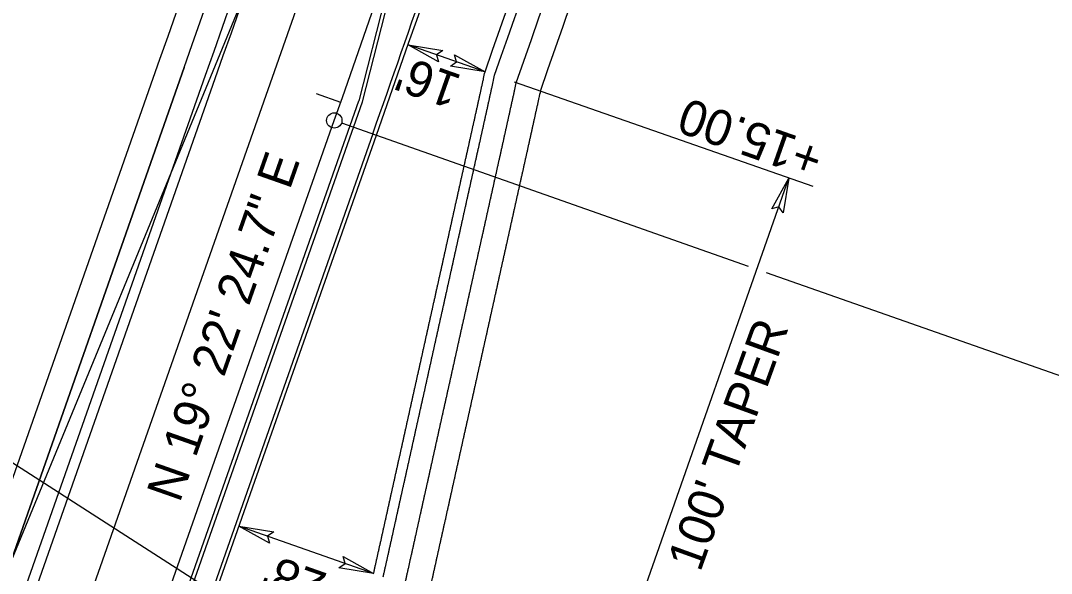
# Model space of a CAD drawing. Extents: x 1974386 to 1979988, y 776712 to 784860.
# Drawn here: x 1977395.6 to 1977597.8, y 780987 to 781095.4 of the extents above; entities that cross this region are included whole.
import ezdxf

# ---------------------------------------------------------------- set-up
doc = ezdxf.new("R2010")
doc.units = 0
for name, color, linetype in [('Prop Conc 2ft 6in Curb and Gutter', 7, 'Continuous'), ('Prop Conc 4in Sidewalk', 7, 'Continuous'), ('Prop Conc 5in Monolithic Keyed In Island', 7, 'Continuous'), ('Prop Dimension', 7, 'Continuous'), ('Prop Dimension Text', 7, 'Continuous'), ('Prop EOT', 7, 'Continuous'), ('Prop Horizontal Alignment', 7, 'Continuous'), ('Prop Horizontal Alignment Direction Label', 7, 'Continuous'), ('Prop Horizontal Alignment Station Label', 7, 'Continuous'), ('Prop Horizontal Alignment Tick Small', 7, 'Continuous'), ('Prop Terminator CELL', 7, 'Continuous'), ('Scratch_Level_1', 7, 'Continuous'), ('Sheet Layout Plan Border', 7, 'Continuous')]:
    doc.layers.add(name, color=color, linetype=linetype)

msp = doc.modelspace()

# ---------------------------------------------------------------- linework, layer by layer
at = {"layer": 'Prop Conc 2ft 6in Curb and Gutter'}
msp.add_line((1977366.39, 780898.48), (1977431.87, 781084.7), dxfattribs=at)
for radius, start, end in [(10973.25, 340.626468, 342.297), (11026.75, 340.72417, 342.033223)]:
    msp.add_arc((1967079.97, 784724.8), radius, start, end, dxfattribs=at)
for points in [[(1977477.64, 781035.49), (1977477.79, 781036.15), (1977477.94, 781036.82), (1977478.08, 781037.48), (1977478.23, 781038.14), (1977478.38, 781038.81), (1977478.53, 781039.47), (1977478.68, 781040.14), (1977478.82, 781040.8), (1977478.97, 781041.47), (1977479.12, 781042.13), (1977479.27, 781042.79), (1977479.41, 781043.46), (1977479.56, 781044.12), (1977479.71, 781044.79), (1977479.86, 781045.45), (1977480, 781046.12), (1977480.15, 781046.78), (1977480.3, 781047.44), (1977480.45, 781048.11), (1977480.59, 781048.77), (1977480.74, 781049.44), (1977480.89, 781050.1), (1977481.04, 781050.77), (1977481.19, 781051.43), (1977481.33, 781052.09), (1977481.48, 781052.76), (1977481.63, 781053.42), (1977481.78, 781054.09), (1977481.92, 781054.75), (1977482.07, 781055.42), (1977482.22, 781056.08), (1977482.37, 781056.74), (1977482.51, 781057.41), (1977482.66, 781058.07), (1977482.81, 781058.74), (1977482.96, 781059.4), (1977483.1, 781060.07), (1977483.25, 781060.73), (1977483.4, 781061.39), (1977483.55, 781062.06), (1977483.7, 781062.72), (1977483.84, 781063.39), (1977483.99, 781064.05), (1977484.14, 781064.72), (1977484.29, 781065.38), (1977484.43, 781066.04), (1977484.58, 781066.71), (1977484.73, 781067.38), (1977484.88, 781068.04), (1977485.03, 781068.71), (1977485.17, 781069.37), (1977485.32, 781070.04), (1977485.47, 781070.71), (1977485.62, 781071.37), (1977485.77, 781072.04), (1977485.91, 781072.7), (1977486.06, 781073.37), (1977486.21, 781074.04), (1977486.36, 781074.7), (1977486.5, 781075.37), (1977486.65, 781076.03), (1977486.8, 781076.7), (1977486.95, 781077.37), (1977487.1, 781078.03), (1977487.24, 781078.7), (1977487.39, 781079.37), (1977487.54, 781080.03), (1977487.68, 781080.7), (1977487.83, 781081.36), (1977487.98, 781082.03), (1977488.13, 781082.7), (1977488.27, 781083.36), (1977488.57, 781084.69)], [(1977466.72, 780986.33), (1977466.86, 780986.99), (1977467.01, 780987.66), (1977467.16, 780988.32), (1977467.31, 780988.98), (1977467.45, 780989.65), (1977467.6, 780990.31), (1977467.75, 780990.98), (1977467.9, 780991.64), (1977468.04, 780992.31), (1977468.19, 780992.97), (1977468.34, 780993.63), (1977468.49, 780994.3), (1977468.64, 780994.96), (1977468.78, 780995.63), (1977468.93, 780996.29), (1977469.08, 780996.96), (1977469.23, 780997.62), (1977469.37, 780998.28), (1977469.52, 780998.95), (1977469.67, 780999.61), (1977469.82, 781000.28), (1977469.96, 781000.94), (1977470.11, 781001.61), (1977470.26, 781002.27), (1977470.41, 781002.94), (1977470.55, 781003.6), (1977470.7, 781004.26), (1977470.85, 781004.93), (1977471, 781005.59), (1977471.15, 781006.26), (1977471.29, 781006.92), (1977471.44, 781007.59), (1977471.59, 781008.25), (1977471.74, 781008.91), (1977471.88, 781009.58), (1977472.03, 781010.24), (1977472.18, 781010.91), (1977472.33, 781011.57), (1977472.47, 781012.24), (1977472.62, 781012.9), (1977472.77, 781013.56), (1977472.92, 781014.23), (1977473.06, 781014.89), (1977473.21, 781015.56), (1977473.36, 781016.22), (1977473.51, 781016.89), (1977473.66, 781017.55), (1977473.8, 781018.21), (1977473.95, 781018.88), (1977474.1, 781019.54), (1977474.25, 781020.21), (1977474.39, 781020.87), (1977474.54, 781021.54), (1977474.69, 781022.2), (1977474.84, 781022.86), (1977474.98, 781023.53), (1977475.13, 781024.19), (1977475.28, 781024.86), (1977475.43, 781025.52), (1977475.57, 781026.19), (1977475.72, 781026.85), (1977475.87, 781027.51), (1977476.02, 781028.18), (1977476.17, 781028.84), (1977476.31, 781029.51), (1977476.46, 781030.17), (1977476.61, 781030.84), (1977476.76, 781031.5), (1977476.9, 781032.16), (1977477.05, 781032.83), (1977477.2, 781033.49), (1977477.35, 781034.16), (1977477.49, 781034.82), (1977477.64, 781035.49)]]:
    msp.add_spline(points, degree=3, dxfattribs=at)
at = {"layer": 'Prop Conc 4in Sidewalk'}
for p, q in [((1977357.43, 780901.63), (1977422.91, 781087.85)), ((1977357.43, 780901.63), (1977422.91, 781087.85)), ((1977362.15, 780899.97), (1977427.63, 781086.19)), ((1977427.63, 781086.19), (1977362.15, 780899.97)), ((1977430.16, 780999.18), (1977430.16, 780999.18))]:
    msp.add_line(p, q, dxfattribs=at)
for radius, start in [(10963.75, 340.626468), (10968.75, 340.626468), (11031.25, 340.72417), (11036.25, 340.72417)]:
    msp.add_arc((1967079.97, 784724.8), radius, start, 342.220851, dxfattribs=at)
for points in [[(1977481.89, 781033.99), (1977482.03, 781034.66), (1977482.18, 781035.32), (1977482.33, 781035.99), (1977482.48, 781036.65), (1977482.63, 781037.32), (1977482.77, 781037.98), (1977482.92, 781038.64), (1977483.07, 781039.31), (1977483.22, 781039.97), (1977483.36, 781040.64), (1977483.51, 781041.3), (1977483.66, 781041.97), (1977483.81, 781042.63), (1977483.95, 781043.29), (1977484.1, 781043.96), (1977484.25, 781044.62), (1977484.4, 781045.29), (1977484.54, 781045.95), (1977484.69, 781046.62), (1977484.84, 781047.28), (1977484.99, 781047.94), (1977485.14, 781048.61), (1977485.28, 781049.27), (1977485.43, 781049.94), (1977485.58, 781050.6), (1977485.73, 781051.27), (1977485.87, 781051.93), (1977486.02, 781052.59), (1977486.17, 781053.26), (1977486.32, 781053.92), (1977486.46, 781054.59), (1977486.61, 781055.25), (1977486.76, 781055.92), (1977486.91, 781056.58), (1977487.05, 781057.24), (1977487.2, 781057.91), (1977487.35, 781058.57), (1977487.5, 781059.24), (1977487.65, 781059.9), (1977487.79, 781060.57), (1977487.94, 781061.23), (1977488.09, 781061.89), (1977488.24, 781062.56), (1977488.38, 781063.22), (1977488.53, 781063.89), (1977488.68, 781064.55), (1977488.83, 781065.22), (1977488.98, 781065.88), (1977489.12, 781066.55), (1977489.27, 781067.22), (1977489.42, 781067.88), (1977489.57, 781068.55), (1977489.72, 781069.22), (1977489.86, 781069.88), (1977490.01, 781070.55), (1977490.16, 781071.21), (1977490.31, 781071.88), (1977490.46, 781072.55), (1977490.6, 781073.21), (1977490.75, 781073.88), (1977490.9, 781074.55), (1977491.05, 781075.21), (1977491.19, 781075.88), (1977491.34, 781076.54), (1977491.49, 781077.21), (1977491.64, 781077.88), (1977491.78, 781078.54), (1977491.93, 781079.21), (1977492.08, 781079.88), (1977492.23, 781080.54), (1977492.37, 781081.21), (1977492.52, 781081.88), (1977492.82, 781083.21)], [(1977497.54, 781081.56), (1977497.24, 781080.22), (1977497.09, 781079.56), (1977496.95, 781078.89), (1977496.8, 781078.22), (1977496.65, 781077.56), (1977496.5, 781076.89), (1977496.36, 781076.22), (1977496.21, 781075.56), (1977496.06, 781074.89), (1977495.91, 781074.22), (1977495.77, 781073.56), (1977495.62, 781072.89), (1977495.47, 781072.22), (1977495.32, 781071.56), (1977495.17, 781070.89), (1977495.03, 781070.23), (1977494.88, 781069.56), (1977494.73, 781068.89), (1977494.58, 781068.23), (1977494.43, 781067.56), (1977494.29, 781066.89), (1977494.14, 781066.23), (1977493.99, 781065.56), (1977493.84, 781064.89), (1977493.69, 781064.23), (1977493.54, 781063.56), (1977493.4, 781062.89), (1977493.25, 781062.23), (1977493.1, 781061.56), (1977492.95, 781060.9), (1977492.81, 781060.24), (1977492.66, 781059.57), (1977492.51, 781058.91), (1977492.36, 781058.24), (1977492.21, 781057.58), (1977492.07, 781056.91), (1977491.92, 781056.25), (1977491.77, 781055.59), (1977491.62, 781054.92), (1977491.48, 781054.26), (1977491.33, 781053.59), (1977491.18, 781052.93), (1977491.03, 781052.26), (1977490.89, 781051.6), (1977490.74, 781050.94), (1977490.59, 781050.27), (1977490.44, 781049.61), (1977490.3, 781048.94), (1977490.15, 781048.28), (1977490, 781047.61), (1977489.85, 781046.95), (1977489.7, 781046.29), (1977489.56, 781045.62), (1977489.41, 781044.96), (1977489.26, 781044.29), (1977489.11, 781043.63), (1977488.97, 781042.96), (1977488.82, 781042.3), (1977488.67, 781041.64), (1977488.52, 781040.97), (1977488.38, 781040.31), (1977488.23, 781039.64), (1977488.08, 781038.98), (1977487.93, 781038.31), (1977487.78, 781037.65), (1977487.64, 781036.99), (1977487.49, 781036.32), (1977487.34, 781035.66), (1977487.19, 781034.99), (1977487.05, 781034.33), (1977486.9, 781033.66), (1977486.75, 781033), (1977486.6, 781032.34)], [(1977470.96, 780984.83), (1977471.11, 780985.5), (1977471.26, 780986.16), (1977471.4, 780986.83), (1977471.55, 780987.49), (1977471.7, 780988.16), (1977471.85, 780988.82), (1977471.99, 780989.48), (1977472.14, 780990.15), (1977472.29, 780990.81), (1977472.44, 780991.48), (1977472.59, 780992.14), (1977472.73, 780992.81), (1977472.88, 780993.47), (1977473.03, 780994.13), (1977473.18, 780994.8), (1977473.32, 780995.46), (1977473.47, 780996.13), (1977473.62, 780996.79), (1977473.77, 780997.46), (1977473.91, 780998.12), (1977474.06, 780998.79), (1977474.21, 780999.45), (1977474.36, 781000.11), (1977474.5, 781000.78), (1977474.65, 781001.44), (1977474.8, 781002.11), (1977474.95, 781002.77), (1977475.1, 781003.44), (1977475.24, 781004.1), (1977475.39, 781004.76), (1977475.54, 781005.43), (1977475.69, 781006.09), (1977475.83, 781006.76), (1977475.98, 781007.42), (1977476.13, 781008.09), (1977476.28, 781008.75), (1977476.42, 781009.41), (1977476.57, 781010.08), (1977476.72, 781010.74), (1977476.87, 781011.41), (1977477.01, 781012.07), (1977477.16, 781012.74), (1977477.31, 781013.4), (1977477.46, 781014.06), (1977477.61, 781014.73), (1977477.75, 781015.39), (1977477.9, 781016.06), (1977478.05, 781016.72), (1977478.2, 781017.39), (1977478.34, 781018.05), (1977478.49, 781018.71), (1977478.64, 781019.38), (1977478.79, 781020.04), (1977478.93, 781020.71), (1977479.08, 781021.37), (1977479.23, 781022.04), (1977479.38, 781022.7), (1977479.52, 781023.36), (1977479.67, 781024.03), (1977479.82, 781024.69), (1977479.97, 781025.36), (1977480.12, 781026.02), (1977480.26, 781026.69), (1977480.41, 781027.35), (1977480.56, 781028.01), (1977480.71, 781028.68), (1977480.85, 781029.34), (1977481, 781030.01), (1977481.15, 781030.67), (1977481.3, 781031.34), (1977481.44, 781032), (1977481.59, 781032.67), (1977481.74, 781033.33), (1977481.89, 781033.99)], [(1977486.6, 781032.34), (1977486.46, 781031.67), (1977486.31, 781031.01), (1977486.16, 781030.34), (1977486.01, 781029.68), (1977485.87, 781029.01), (1977485.72, 781028.35), (1977485.57, 781027.68), (1977485.42, 781027.02), (1977485.27, 781026.36), (1977485.13, 781025.69), (1977484.98, 781025.03), (1977484.83, 781024.36), (1977484.68, 781023.7), (1977484.54, 781023.03), (1977484.39, 781022.37), (1977484.24, 781021.71), (1977484.09, 781021.04), (1977483.95, 781020.38), (1977483.8, 781019.71), (1977483.65, 781019.05), (1977483.5, 781018.38), (1977483.36, 781017.72), (1977483.21, 781017.06), (1977483.06, 781016.39), (1977482.91, 781015.73), (1977482.76, 781015.06), (1977482.62, 781014.4), (1977482.47, 781013.73), (1977482.32, 781013.07), (1977482.17, 781012.41), (1977482.03, 781011.74), (1977481.88, 781011.08), (1977481.73, 781010.41), (1977481.58, 781009.75), (1977481.44, 781009.08), (1977481.29, 781008.42), (1977481.14, 781007.76), (1977480.99, 781007.09), (1977480.85, 781006.43), (1977480.7, 781005.76), (1977480.55, 781005.1), (1977480.4, 781004.43), (1977480.25, 781003.77), (1977480.11, 781003.11), (1977479.96, 781002.44), (1977479.81, 781001.78), (1977479.66, 781001.11), (1977479.52, 781000.45), (1977479.37, 780999.78), (1977479.22, 780999.12), (1977479.07, 780998.46), (1977478.93, 780997.79), (1977478.78, 780997.13), (1977478.63, 780996.46), (1977478.48, 780995.8), (1977478.34, 780995.13), (1977478.19, 780994.47), (1977478.04, 780993.8), (1977477.89, 780993.14), (1977477.74, 780992.48), (1977477.6, 780991.81), (1977477.45, 780991.15), (1977477.3, 780990.48), (1977477.15, 780989.82), (1977477.01, 780989.15), (1977476.86, 780988.49), (1977476.71, 780987.83), (1977476.56, 780987.16), (1977476.42, 780986.5), (1977476.27, 780985.83), (1977476.12, 780985.17), (1977475.97, 780984.5), (1977475.83, 780983.84), (1977475.68, 780983.18)]]:
    msp.add_spline(points, degree=3, dxfattribs=at)
at = {"layer": 'Prop Conc 5in Monolithic Keyed In Island'}
for p, q in [((1977462.63, 781079.46), (1977478.18, 781140.13)), ((1977396.53, 780891.48), (1977462.63, 781079.46)), ((1977464.66, 781073.17), (1977400.3, 780890.15))]:
    msp.add_line(p, q, dxfattribs=at)
msp.add_arc((1967079.97, 784724.8), 11008, 340.626468, 340.97892, dxfattribs=at)
at = {"layer": 'Prop Dimension'}
for p, q in [((1977486.68, 781085.35), (1977471.58, 781090.64)), ((1977551.06, 781062.84), (1977492.45, 781083.34)), ((1977513.09, 780970.02), (1977546.3, 781064.48)), ((1977464.83, 780986.99), (1977438.41, 780996.28))]:
    msp.add_line(p, q, dxfattribs=at)
at = {"layer": 'Prop EOT'}
for p, q in [((1977499.26, 781225.36), (1977461.91, 781079.68)), ((1977368.28, 780897.82), (1977433.76, 781084.03)), ((1977395.82, 780891.73), (1977461.91, 781079.68)), ((1977401.01, 780889.9), (1977465.36, 781072.92))]:
    msp.add_line(p, q, dxfattribs=at)
for radius, start in [(10975.25, 340.626468), (11008.75, 340.626468), (11024.75, 340.72417)]:
    msp.add_arc((1967079.97, 784724.8), radius, start, 342.220851, dxfattribs=at)
for points in [[(1977475.75, 781036.15), (1977475.9, 781036.81), (1977476.05, 781037.48), (1977476.2, 781038.14), (1977476.35, 781038.81), (1977476.49, 781039.47), (1977476.64, 781040.14), (1977476.79, 781040.8), (1977476.94, 781041.46), (1977477.08, 781042.13), (1977477.23, 781042.79), (1977477.38, 781043.46), (1977477.53, 781044.12), (1977477.67, 781044.79), (1977477.82, 781045.45), (1977477.97, 781046.11), (1977478.12, 781046.78), (1977478.27, 781047.44), (1977478.41, 781048.11), (1977478.56, 781048.77), (1977478.71, 781049.44), (1977478.86, 781050.1), (1977479, 781050.76), (1977479.15, 781051.43), (1977479.3, 781052.09), (1977479.45, 781052.76), (1977479.59, 781053.42), (1977479.74, 781054.09), (1977479.89, 781054.75), (1977480.04, 781055.41), (1977480.18, 781056.08), (1977480.33, 781056.74), (1977480.48, 781057.41), (1977480.63, 781058.07), (1977480.78, 781058.74), (1977480.92, 781059.4), (1977481.07, 781060.07), (1977481.22, 781060.73), (1977481.37, 781061.39), (1977481.51, 781062.06), (1977481.66, 781062.72), (1977481.81, 781063.39), (1977481.96, 781064.05), (1977482.1, 781064.72), (1977482.25, 781065.38), (1977482.4, 781066.04), (1977482.55, 781066.71), (1977482.69, 781067.37), (1977482.84, 781068.04), (1977482.99, 781068.71), (1977483.14, 781069.37), (1977483.29, 781070.04), (1977483.44, 781070.7), (1977483.58, 781071.37), (1977483.73, 781072.04), (1977483.88, 781072.7), (1977484.03, 781073.37), (1977484.17, 781074.03), (1977484.32, 781074.7), (1977484.47, 781075.36), (1977484.62, 781076.03), (1977484.77, 781076.7), (1977484.91, 781077.36), (1977485.06, 781078.03), (1977485.21, 781078.69), (1977485.35, 781079.36), (1977485.5, 781080.03), (1977485.65, 781080.69), (1977485.8, 781081.36), (1977485.94, 781082.02), (1977486.09, 781082.69), (1977486.24, 781083.36), (1977486.39, 781084.02), (1977486.68, 781085.35)], [(1977464.83, 780986.99), (1977464.98, 780987.66), (1977465.12, 780988.32), (1977465.27, 780988.98), (1977465.42, 780989.65), (1977465.57, 780990.31), (1977465.71, 780990.98), (1977465.86, 780991.64), (1977466.01, 780992.31), (1977466.16, 780992.97), (1977466.31, 780993.63), (1977466.45, 780994.3), (1977466.6, 780994.96), (1977466.75, 780995.63), (1977466.9, 780996.29), (1977467.04, 780996.96), (1977467.19, 780997.62), (1977467.34, 780998.28), (1977467.49, 780998.95), (1977467.63, 780999.61), (1977467.78, 781000.28), (1977467.93, 781000.94), (1977468.08, 781001.61), (1977468.22, 781002.27), (1977468.37, 781002.93), (1977468.52, 781003.6), (1977468.67, 781004.26), (1977468.82, 781004.93), (1977468.96, 781005.59), (1977469.11, 781006.26), (1977469.26, 781006.92), (1977469.41, 781007.58), (1977469.55, 781008.25), (1977469.7, 781008.91), (1977469.85, 781009.58), (1977470, 781010.24), (1977470.14, 781010.91), (1977470.29, 781011.57), (1977470.44, 781012.23), (1977470.59, 781012.9), (1977470.73, 781013.56), (1977470.88, 781014.23), (1977471.03, 781014.89), (1977471.18, 781015.56), (1977471.33, 781016.22), (1977471.47, 781016.88), (1977471.62, 781017.55), (1977471.77, 781018.21), (1977471.92, 781018.88), (1977472.06, 781019.54), (1977472.21, 781020.21), (1977472.36, 781020.87), (1977472.51, 781021.53), (1977472.65, 781022.2), (1977472.8, 781022.86), (1977472.95, 781023.53), (1977473.1, 781024.19), (1977473.24, 781024.86), (1977473.39, 781025.52), (1977473.54, 781026.19), (1977473.69, 781026.85), (1977473.84, 781027.51), (1977473.98, 781028.18), (1977474.13, 781028.84), (1977474.28, 781029.51), (1977474.43, 781030.17), (1977474.57, 781030.84), (1977474.72, 781031.5), (1977474.87, 781032.16), (1977475.02, 781032.83), (1977475.16, 781033.49), (1977475.31, 781034.16), (1977475.46, 781034.82), (1977475.61, 781035.49), (1977475.75, 781036.15)]]:
    msp.add_spline(points, degree=3, dxfattribs=at)
at = {"layer": 'Prop Horizontal Alignment'}
msp.add_line((1977307.82, 780651.27), (1977457.11, 781075.82), dxfattribs=at)
msp.add_arc((1967079.97, 784724.8), 11000, 340.626468, 342.220851, dxfattribs=at)
at = {"layer": 'Prop Horizontal Alignment Station Label'}
for p, q in [((1977458.53, 781075.33), (1977538.33, 781047.26)), ((1977541.84, 781046.03), (1977638.27, 781012.12))]:
    msp.add_line(p, q, dxfattribs=at)
msp.add_circle((1977457.11, 781075.82), 1.5, dxfattribs=at)
at = {"layer": 'Prop Horizontal Alignment Tick Small'}
msp.add_line((1977458.36, 781079.37), (1977453.64, 781081.03), dxfattribs=at)
at = {"layer": 'Prop Terminator CELL'}
for points in [[(1977477.56, 781087.31), (1977471.58, 781090.64), (1977478.38, 781089.53), (1977477.17, 781088.68)], [(1977480.69, 781088.68), (1977486.68, 781085.35), (1977479.88, 781086.46), (1977481.09, 781087.31)], [(1977542.96, 781058.5), (1977546.3, 781064.48), (1977545.18, 781057.68), (1977544.33, 781058.89)], [(1977444.4, 780992.94), (1977438.41, 780996.28), (1977445.22, 780995.16), (1977444, 780994.31)], [(1977444.4, 780992.94), (1977438.41, 780996.28), (1977445.22, 780995.16), (1977444, 780994.31)], [(1977444.4, 780992.94), (1977438.41, 780996.28), (1977445.22, 780995.16), (1977444, 780994.31)], [(1977458.85, 780990.33), (1977464.83, 780986.99), (1977458.03, 780988.11), (1977459.24, 780988.96)]]:
    msp.add_lwpolyline(points, close=True, dxfattribs=at)
at = {"layer": 'Scratch_Level_1'}
for p, q in [((1977516.04, 781286.37), (1977329.74, 780834.25)), ((1977356.9, 780833.79), (1977516.04, 781286.37))]:
    msp.add_line(p, q, dxfattribs=at)
at = {"layer": 'Sheet Layout Plan Border'}
msp.add_lwpolyline([(1977111.11, 779526.05), (1977868.38, 780703.57), (1976985.24, 781271.52), (1976227.97, 780094)], close=True, dxfattribs=at)

# ---------------------------------------------------------------- texts
at = {"layer": 'Prop Dimension Text'}
for s, rotation, p in [("16'", 160.6265, (1977482.39, 781084.57)), ('+15.00', 160.6265, (1977553.52, 781070.76)), ("100' TAPER", 70.1136, (1977528.89, 780987.07)), ("28'", 160.6265, (1977456.01, 780986.86))]:
    msp.add_text(s, height=7, rotation=rotation, dxfattribs=at).set_placement(p)
at = {"layer": 'Prop Horizontal Alignment Direction Label'}
msp.add_text('N 19%%d 22\' 24.7" E', height=7, rotation=70.6265, dxfattribs=at).set_placement((1977426.77, 781000.66))

doc.saveas('drawing.dxf')
